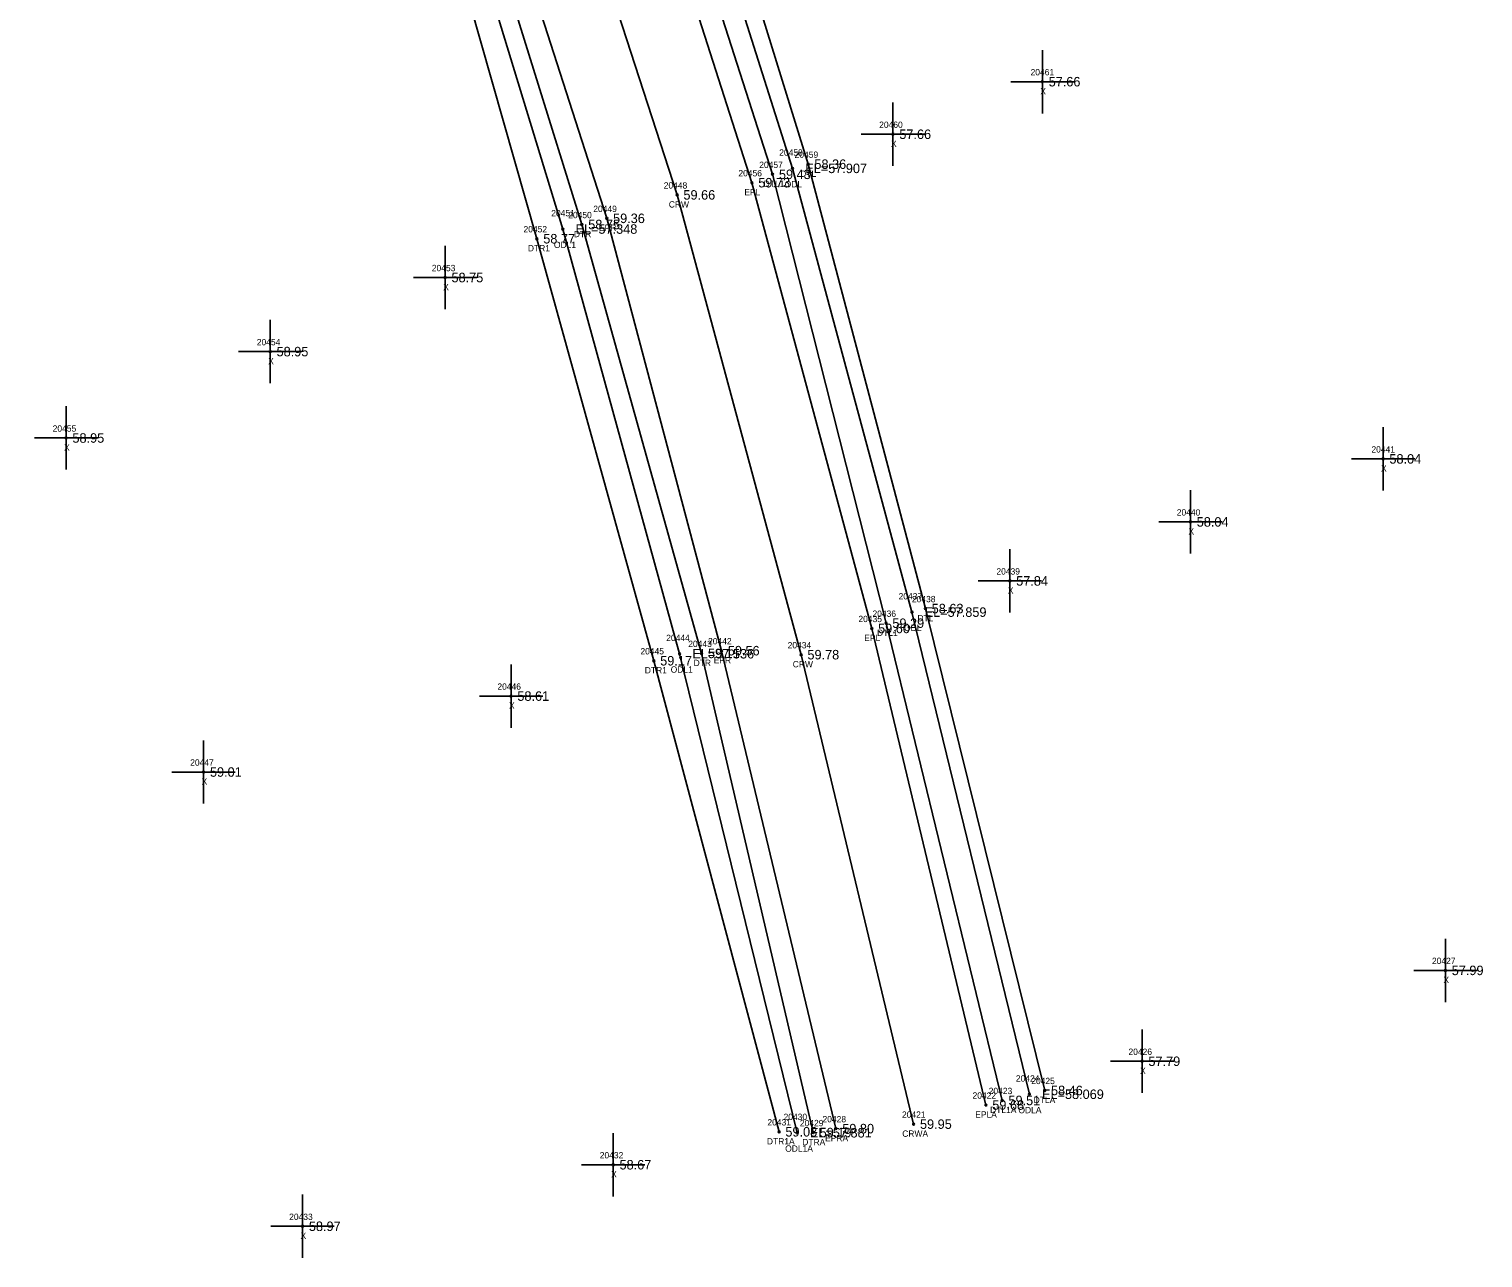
# Model space of a CAD drawing. Extents: x 2396547 to 2397655, y 770185 to 772649.
# Drawn here: x 2397425.8 to 2397655.3, y 770185.1 to 770379.1 of the extents above; entities that cross this region are included whole.
import ezdxf

# ---------------------------------------------------------------- set-up
doc = ezdxf.new("R2010")
doc.units = 0
for name, color, linetype in [('RD_DTM_BkLn1', 7, 'Continuous'), ('RD_EX_H2O', 7, 'Continuous'), ('RD_EX_H2O_txCode', 7, 'Continuous'), ('RD_EX_Misc', 7, 'Continuous'), ('RD_EX_Misc_txCode', 7, 'Continuous'), ('RD_EX_Road', 7, 'Continuous'), ('RD_EX_Road_txCode', 7, 'Continuous'), ('RD_EX_TX_H2O_ELEV', 7, 'Continuous'), ('RD_EX_TX_Misc_ELEV', 7, 'Continuous'), ('RD_EX_TX_Road_ELEV', 7, 'Continuous'), ('RD_HC_Survey_ELEV', 7, 'Continuous'), ('RD_HC_Survey_txCode', 7, 'Continuous'), ('RD_SMD_Locator', 7, 'Continuous')]:
    doc.layers.add(name, color=color, linetype=linetype)

msp = doc.modelspace()

# ---------------------------------------------------------------- linework, layer by layer
at = {"layer": 'RD_DTM_BkLn1'}
msp.add_lwpolyline([(2397565.46, 770206.19), (2397547.69, 770280.33), (2397528.11, 770352.94), (2397504.84, 770424.66), (2397476.69, 770499.34), (2397447.19, 770566.69), (2397412.23, 770635.13), (2397363.03, 770719.95), (2397270.14, 770871.5)], dxfattribs=at)
at = {"layer": 'RD_EX_H2O'}
for points in [[(2397586.15, 770211.51), (2397567.31, 770287.61), (2397548.79, 770357.79), (2397525.19, 770434.22), (2397495.53, 770510.39), (2397465.51, 770576.5), (2397430.55, 770645.5), (2397380.29, 770734.7), (2397327.01, 770824.44), (2397291.42, 770882.36)], [(2397579.43, 770209.93), (2397561.1, 770285.3), (2397543.19, 770356.19), (2397518.98, 770431.67), (2397489.88, 770507.8), (2397460.56, 770573.86), (2397425.02, 770642.83), (2397373.6, 770730.3), (2397319.08, 770819.92), (2397284.14, 770878.8)], [(2397583.73, 770210.91), (2397565.2, 770287.05), (2397546.34, 770357.13), (2397522.25, 770433.23), (2397493.26, 770509.76), (2397463.19, 770575.43), (2397428.34, 770644.33), (2397377.24, 770732.42), (2397321.77, 770821.7), (2397287.01, 770879.96)], [(2397544.21, 770204.98), (2397524.44, 770279.37), (2397505.98, 770346.02), (2397484.83, 770420.44), (2397457.62, 770489.91), (2397433.59, 770544.23), (2397438.3, 770546.59)], [(2397549.62, 770204.86), (2397531.98, 770280.53), (2397513.08, 770348.26), (2397490.2, 770421.93), (2397463.3, 770492), (2397438.3, 770546.59)], [(2397547.08, 770204.83), (2397528.51, 770280.48), (2397510.07, 770347.55), (2397487.52, 770421.4), (2397460.59, 770491.08), (2397436.81, 770542.67)]]:
    msp.add_lwpolyline(points, dxfattribs=at)
at = {"layer": 'RD_EX_Misc'}
for p, q in [((2397585.78, 770365.82), (2397585.78, 770375.82)), ((2397580.78, 770370.82), (2397590.78, 770370.82)), ((2397562.2, 770357.52), (2397562.2, 770367.52)), ((2397557.2, 770362.52), (2397567.2, 770362.52)), ((2397491.49, 770334.89), (2397491.49, 770344.89)), ((2397486.49, 770339.89), (2397496.49, 770339.89)), ((2397463.87, 770323.19), (2397463.87, 770333.19)), ((2397458.87, 770328.19), (2397468.87, 770328.19)), ((2397431.64, 770309.55), (2397431.64, 770319.55)), ((2397639.58, 770306.25), (2397639.58, 770316.25)), ((2397426.64, 770314.55), (2397436.64, 770314.55)), ((2397634.58, 770311.25), (2397644.58, 770311.25)), ((2397609.16, 770296.3), (2397609.16, 770306.3)), ((2397604.16, 770301.3), (2397614.16, 770301.3)), ((2397580.65, 770286.98), (2397580.65, 770296.98)), ((2397575.65, 770291.98), (2397585.65, 770291.98)), ((2397501.89, 770268.79), (2397501.89, 770278.79)), ((2397496.89, 770273.79), (2397506.89, 770273.79)), ((2397453.35, 770256.8), (2397453.35, 770266.8)), ((2397448.35, 770261.8), (2397458.35, 770261.8)), ((2397649.42, 770225.47), (2397649.42, 770235.47)), ((2397644.42, 770230.47), (2397654.42, 770230.47)), ((2397601.53, 770211.12), (2397601.53, 770221.12)), ((2397596.53, 770216.12), (2397606.53, 770216.12)), ((2397518.02, 770194.78), (2397518.02, 770204.78)), ((2397513.02, 770199.78), (2397523.02, 770199.78)), ((2397468.97, 770185.06), (2397468.97, 770195.06)), ((2397463.97, 770190.06), (2397473.97, 770190.06))]:
    msp.add_line(p, q, dxfattribs=at)
at = {"layer": 'RD_EX_Road'}
for points in [[(2397576.88, 770209.21), (2397558.85, 770284.47), (2397539.93, 770354.87), (2397515.81, 770430.13), (2397486.97, 770506.75), (2397457.82, 770572.7), (2397422.37, 770641.75), (2397371.16, 770729.12), (2397316.57, 770818.52), (2397280.76, 770876.73)], [(2397553.19, 770205.48), (2397535.12, 770280.96), (2397517, 770349.24), (2397493.4, 770422.78), (2397467.13, 770492.9), (2397441.16, 770551.74), (2397436.66, 770561.67), (2397402.21, 770629.28), (2397353, 770712.83), (2397296, 770806.32), (2397260.16, 770864.73)]]:
    msp.add_lwpolyline(points, dxfattribs=at)
at = {"layer": 'RD_SMD_Locator'}
for centre in [(2397585.78, 770370.82), (2397562.2, 770362.52), (2397548.79, 770357.79), (2397543.19, 770356.19), (2397546.34, 770357.13), (2397528.11, 770352.94), (2397539.93, 770354.87), (2397513.08, 770348.26), (2397517, 770349.24), (2397505.98, 770346.02), (2397510.07, 770347.55), (2397491.49, 770339.89), (2397463.87, 770328.19), (2397431.64, 770314.55), (2397639.58, 770311.25), (2397609.16, 770301.3), (2397580.65, 770291.98), (2397565.2, 770287.05), (2397567.31, 770287.61), (2397558.85, 770284.47), (2397561.1, 770285.3), (2397524.44, 770279.37), (2397528.51, 770280.48), (2397531.98, 770280.53), (2397535.12, 770280.96), (2397547.69, 770280.33), (2397501.89, 770273.79), (2397453.35, 770261.8), (2397649.42, 770230.47), (2397601.53, 770216.12), (2397583.73, 770210.91), (2397586.15, 770211.51), (2397576.88, 770209.21), (2397579.43, 770209.93), (2397565.46, 770206.19), (2397544.21, 770204.98), (2397547.08, 770204.83), (2397549.62, 770204.86), (2397553.19, 770205.48), (2397518.02, 770199.78), (2397468.97, 770190.06)]:
    msp.add_circle(centre, 0.15, dxfattribs=at)

# ---------------------------------------------------------------- texts
at = {"layer": 'RD_EX_H2O_txCode'}
for s, p in [('20458', (2397544.23, 770359.13)), ('20459', (2397546.67, 770358.79)), ('20457', (2397541.08, 770357.19)), ('DTL1', (2397541.78, 770354.19)), ('ODL', (2397545.1, 770354.13)), ('DTL', (2397547.54, 770355.79)), ('20451', (2397508.24, 770349.55)), ('20450', (2397510.92, 770349.26)), ('20452', (2397503.86, 770347.02)), ('DTR', (2397511.81, 770346.26)), ('DTR1', (2397504.55, 770344.02)), ('ODL1', (2397508.66, 770344.55)), ('20437', (2397563.08, 770289.05)), ('20438', (2397565.19, 770288.61)), ('20436', (2397558.96, 770286.3)), ('DTL', (2397566.06, 770285.61)), ('DTL1', (2397559.69, 770283.3)), ('ODL', (2397563.95, 770284.05)), ('20444', (2397526.39, 770282.48)), ('20443', (2397529.87, 770281.53)), ('20445', (2397522.32, 770280.37)), ('DTR', (2397530.72, 770278.53)), ('DTR1', (2397523.01, 770277.37)), ('ODL1', (2397527.1, 770277.48)), ('20424', (2397581.61, 770212.91)), ('20425', (2397584.03, 770212.51)), ('20423', (2397577.31, 770210.93)), ('DTLA', (2397584.41, 770209.51)), ('DTL1A', (2397577.53, 770207.93)), ('ODLA', (2397582, 770207.91)), ('20431', (2397542.37, 770205.98)), ('20430', (2397544.92, 770206.83)), ('20429', (2397547.5, 770205.86)), ('DTR1A', (2397542.29, 770202.98)), ('DTRA', (2397547.87, 770202.86)), ('ODL1A', (2397545.18, 770201.83))]:
    msp.add_text(s, height=1, dxfattribs=at).set_placement(p)
at = {"layer": 'RD_EX_Misc_txCode'}
for s, p in [('20461', (2397583.92, 770371.82)), ('X', (2397585.46, 770368.82)), ('20460', (2397560.02, 770363.52)), ('X', (2397561.88, 770360.52)), ('20453', (2397489.38, 770340.89)), ('X', (2397491.18, 770337.89)), ('20454', (2397461.75, 770329.19)), ('X', (2397463.55, 770326.19)), ('20455', (2397429.52, 770315.55)), ('X', (2397431.32, 770312.55)), ('20441', (2397637.74, 770312.25)), ('X', (2397639.26, 770309.25)), ('20440', (2397607.01, 770302.3)), ('X', (2397608.85, 770299.3)), ('20439', (2397578.53, 770292.98)), ('X', (2397580.33, 770289.98)), ('20446', (2397499.74, 770274.79)), ('X', (2397501.57, 770271.79)), ('20447', (2397451.23, 770262.8)), ('X', (2397453.03, 770259.8)), ('20427', (2397647.3, 770231.47)), ('X', (2397649.11, 770228.47)), ('20426', (2397599.38, 770217.12)), ('X', (2397601.21, 770214.12)), ('20432', (2397515.9, 770200.78)), ('X', (2397517.7, 770197.78)), ('20433', (2397466.86, 770191.06)), ('X', (2397468.66, 770188.06))]:
    msp.add_text(s, height=1, dxfattribs=at).set_placement(p)
at = {"layer": 'RD_EX_Road_txCode'}
for s, p in [('20456', (2397537.79, 770355.87)), ('EPL', (2397538.73, 770352.87)), ('20449', (2397514.88, 770350.24)), ('EPR', (2397515.77, 770347.24)), ('20435', (2397556.74, 770285.47)), ('20442', (2397533, 770281.96)), ('EPL', (2397557.65, 770282.47)), ('EPR', (2397533.89, 770278.96)), ('20422', (2397574.76, 770210.21)), ('EPLA', (2397575.18, 770207.21)), ('20428', (2397551.07, 770206.48)), ('EPRA', (2397551.47, 770203.48))]:
    msp.add_text(s, height=1, dxfattribs=at).set_placement(p)
at = {"layer": 'RD_EX_TX_H2O_ELEV'}
for s, p in [('EL=57.907', (2397548.34, 770356.38)), ('58.36', (2397549.79, 770357.04)), ('59.43', (2397544.19, 770355.44)), ('EL=57.348', (2397512.07, 770346.8)), ('58.75', (2397514.08, 770347.51)), ('58.77', (2397506.98, 770345.27)), ('EL=57.859', (2397567.2, 770286.3)), ('58.63', (2397568.31, 770286.86)), ('59.29', (2397562.1, 770284.55)), ('59.17', (2397525.44, 770278.62)), ('EL=57.536', (2397530.51, 770279.73)), ('59.11', (2397532.98, 770279.78)), ('59.51', (2397580.43, 770209.18)), ('EL=58.069', (2397585.73, 770210.16)), ('58.46', (2397587.15, 770210.76)), ('59.08', (2397545.21, 770204.23)), ('EL=57.881', (2397549.08, 770204.08)), ('59.19', (2397550.62, 770204.11))]:
    msp.add_text(s, height=1.5, dxfattribs=at).set_placement(p)
at = {"layer": 'RD_EX_TX_Misc_ELEV'}
for s, p in [('57.66', (2397586.78, 770370.07)), ('57.66', (2397563.2, 770361.77)), ('58.75', (2397492.49, 770339.14)), ('58.95', (2397464.87, 770327.44)), ('58.95', (2397432.64, 770313.8)), ('58.04', (2397640.58, 770310.5)), ('58.04', (2397610.16, 770300.55)), ('57.84', (2397581.65, 770291.23)), ('58.61', (2397502.89, 770273.04)), ('59.01', (2397454.35, 770261.05)), ('57.99', (2397650.42, 770229.72)), ('57.79', (2397602.53, 770215.37)), ('58.67', (2397519.02, 770199.03)), ('58.97', (2397469.97, 770189.31))]:
    msp.add_text(s, height=1.5, dxfattribs=at).set_placement(p)
at = {"layer": 'RD_EX_TX_Road_ELEV'}
for s, p in [('59.73', (2397540.93, 770354.12)), ('59.36', (2397518, 770348.49)), ('59.60', (2397559.85, 770283.72)), ('59.56', (2397536.12, 770280.21)), ('59.68', (2397577.88, 770208.46)), ('59.80', (2397554.19, 770204.73))]:
    msp.add_text(s, height=1.5, dxfattribs=at).set_placement(p)
at = {"layer": 'RD_HC_Survey_ELEV'}
for s, p in [('59.66', (2397529.11, 770352.19)), ('59.78', (2397548.69, 770279.58)), ('59.95', (2397566.46, 770205.44))]:
    msp.add_text(s, height=1.5, dxfattribs=at).set_placement(p)
at = {"layer": 'RD_HC_Survey_txCode'}
for s, p in [('20448', (2397526, 770353.94)), ('CRW', (2397526.8, 770350.94)), ('20434', (2397545.57, 770281.33)), ('CRW', (2397546.37, 770278.33)), ('20421', (2397563.62, 770207.19)), ('CRWA', (2397563.66, 770204.19))]:
    msp.add_text(s, height=1, dxfattribs=at).set_placement(p)

doc.saveas('drawing.dxf')
